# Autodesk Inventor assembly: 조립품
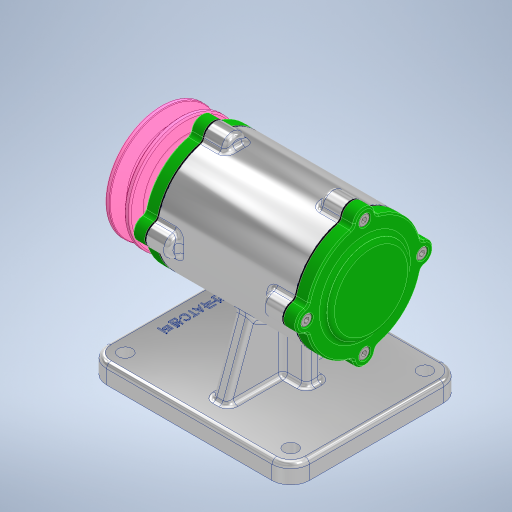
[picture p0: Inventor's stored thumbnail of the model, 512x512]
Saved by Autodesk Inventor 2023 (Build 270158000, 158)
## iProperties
Created: 2023-08
Part Number: 조립품
Document SubType Name: Assembly
Designer: asung
Author: asung
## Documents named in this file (12)
- C:\Users\asung\Desktop\730808V1009\조립품.iam
- C:\Users\asung\Desktop\730808V1009\본체.ipt
- C:\Users\asung\Desktop\730808V1009\앞커버.ipt
- C:\Users\asung\Desktop\730808V1009\뒤커버.ipt
- C:\Users\asung\Desktop\730808V1009\베어링 6204.ipt
- C:\Users\asung\Desktop\730808V1009\개스킷.ipt
- C:\Users\asung\Desktop\730808V1009\축.ipt
- C:\Users\asung\Desktop\730808V1009\오일 실.ipt
- C:\Users\asung\Desktop\730808V1009\볼트 M4 x 12.ipt
- C:\Users\asung\Desktop\730808V1009\키 4 x 4.ipt
- C:\Users\asung\Desktop\730808V1009\V-벨트풀리.ipt
- C:\Users\asung\Desktop\730808V1009\너트 M12 x 1.25.ipt
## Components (8 placed, 6 different names)
1. 개스킷:1
2. 개스킷:2
3. KS B 2023 6204 - 20 x 47 x 14:1
4. KS B 2023 6204 - 20 x 47 x 14:2
5. KS B 2804 D D - 20 32 8:1
6. KS B 1311 (I) 4 x 4 x 12:1
7. V-벨트풀리:1
8. KS B 1012 클래스 1 일반 - 미터 M12x1.25:1
